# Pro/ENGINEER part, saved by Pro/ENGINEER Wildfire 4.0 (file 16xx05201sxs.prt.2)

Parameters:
  HERSTELLER = "Hersteller"
  PSOL_NOTUSEDSKLST = "SKLST{SKETCH{NAME{"Sketch 8"}MAT{1,0,0,0,0,0,-1,0,0,1,0,0,0,-0.5,0,1}SKETCH"
  NB = "16XX05201SXS"
  NN = "16-S2"
  NT = "16 Series - Swivel - Yoke Base"
  NBSYN = "$PN.$RIGS.$T."
  LINA = "16XX05201SXS"
  PN = "16XX05201"
  RIGS = "S"
  T = "XS"
  DIA = "5"
  WIDTH = "2"
  A = "2.43750000"
  B = "3.25000000"
  C = "1.62500000"
  D = "4.00000000"
  WW1 = "2.000"
  E = "1.630"
  F = "2.600"
  H = "0.150"
  I = "0.100"
  J = "0.130"
  K = "0.310"
  T1 = "'XS','MR','PB','XA','CA','TM','NG','XI','PI','PD','XP','CH'"
  PN1 = "XS0520112"
  AXLE = "1"
  Z = "1.000"
  KT = "DUMMY"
